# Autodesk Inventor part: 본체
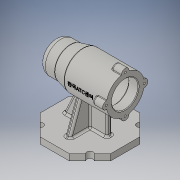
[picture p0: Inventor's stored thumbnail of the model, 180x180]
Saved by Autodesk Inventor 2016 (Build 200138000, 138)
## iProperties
Created: 2019-12
Part Number: 본체
Material: Generic
Document SubType Name: Modeling
Designer: MIRAE
Density: 1 g/cm^3
Appearance: Default
Mass: 268.559 g
Surface Area: 716.328 cm^2
Volume: 268.559 cm^3
Author: MIRAE
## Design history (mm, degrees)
sketch "스케치1"
  geometry: L1 (56, 0)-(-56, 0); L2 (0, -6)-(0, 36) reference; L3 (-56, 0)-(-56, 30); L4 (-56, 30)-(11, 30); L5 (56, 0)-(56, 25); L6 (56, 25)-(31, 25); L7 (31, 25)-(11, 30); 1 further point
  constraints: 12 end point, 2 perpendicular, 1 horizontal, 1 parallel, 1 symmetric about line, 1 vertical
  dimensions: "d0" = 112 distance of L1.start L1.end; "d1" = 30 distance of L1.end L3.end; "d2" = 67 distance of L3.end L4.end; "d3" = 25 distance of L1.start L5.end; "d4" = 25 distance of L5.end L6.end; "d5" = 30 distance from line of L4 point (0, 0)
revolve "회전1" sketch "스케치1" stored, may be unused: angle "d6" = 90 deg
sketch "스케치2"
  geometry: L1 (-56, -30)-(-56, 30) reference; L2 (-56, 0)-(-56, 21); L3 (-56, 21)-(-41, 21); L4 (-41, 21)-(-41, 21); L5 (-38, 24)-(10, 24); L6 (13, 21)-(13, 21); L7 (13, 21)-(24.7, 21); L8 (25, 20.7)-(25, 17.5); L9 (25, 17.5)-(42.7, 17.5); L10 (43, 17.2)-(43, 16); L11 (43, 16)-(46.7, 16); L12 (47, 15.7)-(47, 10.5); L13 (47, 10.5)-(47, 10.5); L14 (56, -25)-(56, 25) reference; L15 (0, 0)-(50, 0); L16 (50, 0)-(50, 7.5); L17 (0, 0)-(-56, 0); A1 r 0.3 centre (46.7, 15.7) between (47, 15.7) and (46.7, 16); A2 r 0.3 centre (42.7, 17.2) between (43, 17.2) and (42.7, 17.5); A3 r 0.3 centre (24.7, 20.7) between (25, 20.7) and (24.7, 21); A4 r 3 centre (10, 21) between (13, 21) and (10, 24); A5 r 3 centre (-38, 21) between (-38, 24) and (-41, 21); A6 r 3 centre (47, 7.5) between (50, 7.5) and (47, 10.5); 6 further points
  constraints: 30 end point, 15 point on line, 12 point on circle, 12 tangent, 10 perpendicular, 6 centre point, 3 equal radius, 1 horizontal, 1 midpoint, 1 vertical
  dimensions: "d7" = 21 distance of L2.start L2.end; "d8" = 15 distance of L2.end L3.end; "d9" = 3 distance of L3.end point (-41, 24); "d10" = 54 distance of point (-41, 24) point (13, 24); "d11" = 3 distance of point (13, 24) L6.end; "d12" = 12 distance of L6.end point (25, 21); "d13" = 3.5 distance of point (25, 21) L8.end; "d14" = 18 distance of L8.end point (43, 17.5); "d15" = 1.5 distance of point (43, 17.5) L10.end; "d16" = 4 distance of L10.end point (47, 16); "d17" = 5.5 distance of point (47, 16) L12.end; "d18" = 3 distance of L12.end point (50, 10.5); "d22" = 0.3 radius of A1; "d72" = 3 radius of A4; "d78" = 3 radius of A6
revolve "회전2" sketch "스케치2" stored, may be unused: angle "d20" = 90 deg
fillet "모깎기1" dims "d21" = 10
sketch "스케치3"
  geometry: L1 (0, 0)-(-30, 0); C1 r 6 at (-30, 0)
  constraints: 2 end point, 1 centre point, 1 coincident, 1 horizontal
  dimensions: "d23" = 30 distance of L1.start L1.end; "d24" = 12 diameter of C1
extrude "돌출1" join sketch "스케치3" distance "d25" = 16; taper "d26" = 0 deg
sketch "스케치4"
  geometry: L1 (30, 0)-(0, 0)
  constraints: 2 end point, 1 horizontal
  dimensions: "d27" = 30 distance of L1.start L1.end
hole "구멍1" sketch "스케치4" at (0, 0) diameter "d28" = 3.242; stored, may be unused: countersink angle "d32" = 82 deg, drill point angle "d34" = 118 deg; dims "d29" = 8, "d30" = 3.023, "d31" = 2, "d33" = 11
fillet "모깎기2" dims "d38" = 3
fillet "모깎기3" dims "d39" = 1
node "작업 평면1"
sketch "스케치5" dims "d42" = 112
  geometry: L1 (-78.4, 0)-(78.4, 0) reference; L2 (0, -50.4)-(0, 50.4) reference; L3 (23.196, -56)-(-23.196, -56); L4 (-23.196, -56)-(-56, -23.196); L5 (-56, -23.196)-(-56, 23.196); L6 (-56, 23.196)-(-23.196, 56); L7 (-23.196, 56)-(23.196, 56); L8 (23.196, 56)-(56, 23.196); L9 (56, 23.196)-(56, -23.196); L10 (56, -23.196)-(23.196, -56); 4 further points
  constraints: 16 end point, 2 coincident, 1 midpoint, 1 vertical, 20 other
extrude "돌출2" join sketch "스케치5" distance "d43" = 10; taper "d44" = 0 deg
sketch "스케치6"
  geometry: L1 (0, 0)-(-39.598, 39.598); L2 (-56, 23.196)-(-23.196, 56) reference; L3 (0, 0)-(-39.598, -39.598); L4 (-23.196, -56)-(-56, -23.196) reference; L5 (0, -78.4)-(0, 78.4) reference; L6 (-78.4, 0)-(78.4, 0) reference; L7 (0, 0)-(39.598, 39.598); L8 (23.196, 56)-(56, 23.196) reference; L9 (0, 0)-(39.598, -39.598); L10 (56, -23.196)-(23.196, -56) reference
  constraints: 8 end point, 4 midpoint
hole "구멍2" sketch "스케치6" at (-39.598, -39.598), (39.598, -39.598), (39.598, 39.598), (-39.598, 39.598) diameter "d45" = 10; stored, may be unused: countersink angle "d49" = 82 deg, drill point angle "d51" = 0 deg; dims "d46" = 8, "d47" = 3.023, "d48" = 2, "d50" = 11
chamfer "모따기1" distance "d52" = 1; stored, may be unused: second distance "d53" = 2, angle "d54" = 45 deg
sketch "스케치7"
  geometry: L1 (-43.134, -70)-(-56, -70) reference; L2 (56, -70)-(43.134, -70) reference; L3 (36, -70)-(18.13, -20.903); L4 (-56, -80)-(-56, -70) reference; L5 (56, -80)-(56, -70) reference; C1 r 30 at (0, 0) reference; 1 further point
  constraints: 2 end point, 1 point on line
  dimensions: "d56" = 20 distance from line of L5 L3.start; "d57" = 110 deg angle of L2 L3
sketch "스케치8"
  geometry: L1 (-31, -70)-(-31, -28.131); L2 (38, -70)-(18.476, -28.131); L3 (-56, -80)-(-56, -70) reference; L4 (56, -80)-(56, -70) reference; L5 (43.134, -70)-(56, -70) reference; L6 (23.196, -70)-(36.062, -70) reference; L7 (38, -70)-(-31, -70); L8 (-23.196, -70)-(23.196, -70) reference; L9 (18.476, -28.131)-(-31, -28.131); L10 (-39, -30)-(11, -30) reference; 2 further points
  constraints: 8 end point, 1 collinear, 1 parallel, 1 point on line, 1 vertical
  dimensions: "d58" = 25 distance between parallel lines of L1 L3; "d59" = 18 distance from line of L4 L2.start; "d60" = 115 deg angle of L5 L2; "d76" = 41.86904 distance between parallel lines of L7 L9
extrude "돌출3" join sketch "스케치8" stored distance "d61" = 8; taper "d62" = 0 deg
feature "리브1" dims "d63" = 1, "d64" = 8, "d65" = 0, "d66" = 0, "d67" = 1, "d68" = 1
fillet "모깎기4" dims "d69" = 3
fillet "모깎기5" dims "d70" = 3
fillet "모깎기6" dims "d71" = 3
node "작업 평면2"
sketch "스케치9"
  geometry: L1 (33.5, 29.226)-(33.5, 6.771) reference; L2 (-100.9, 0)-(55.9, 0) reference; 2 further points
  constraints: 1 point on line, 1 other
  dimensions: "d73" = 41 distance from line of L1 point (-7.5, 0)
feature "엠보싱1" sketch "스케치9" dims "d0" = 112, "d1" = 30, "d2" = 67, "d3" = 25, "d4" = 25, "d5" = 30, "d74" = 0.5, "d75" = 0
fillet "모깎기7" dims "d77" = 3
node "솔리드1"
pattern_circular "원형 패턴1" dims angle "d36" = 360 deg
mirror "대칭1"
